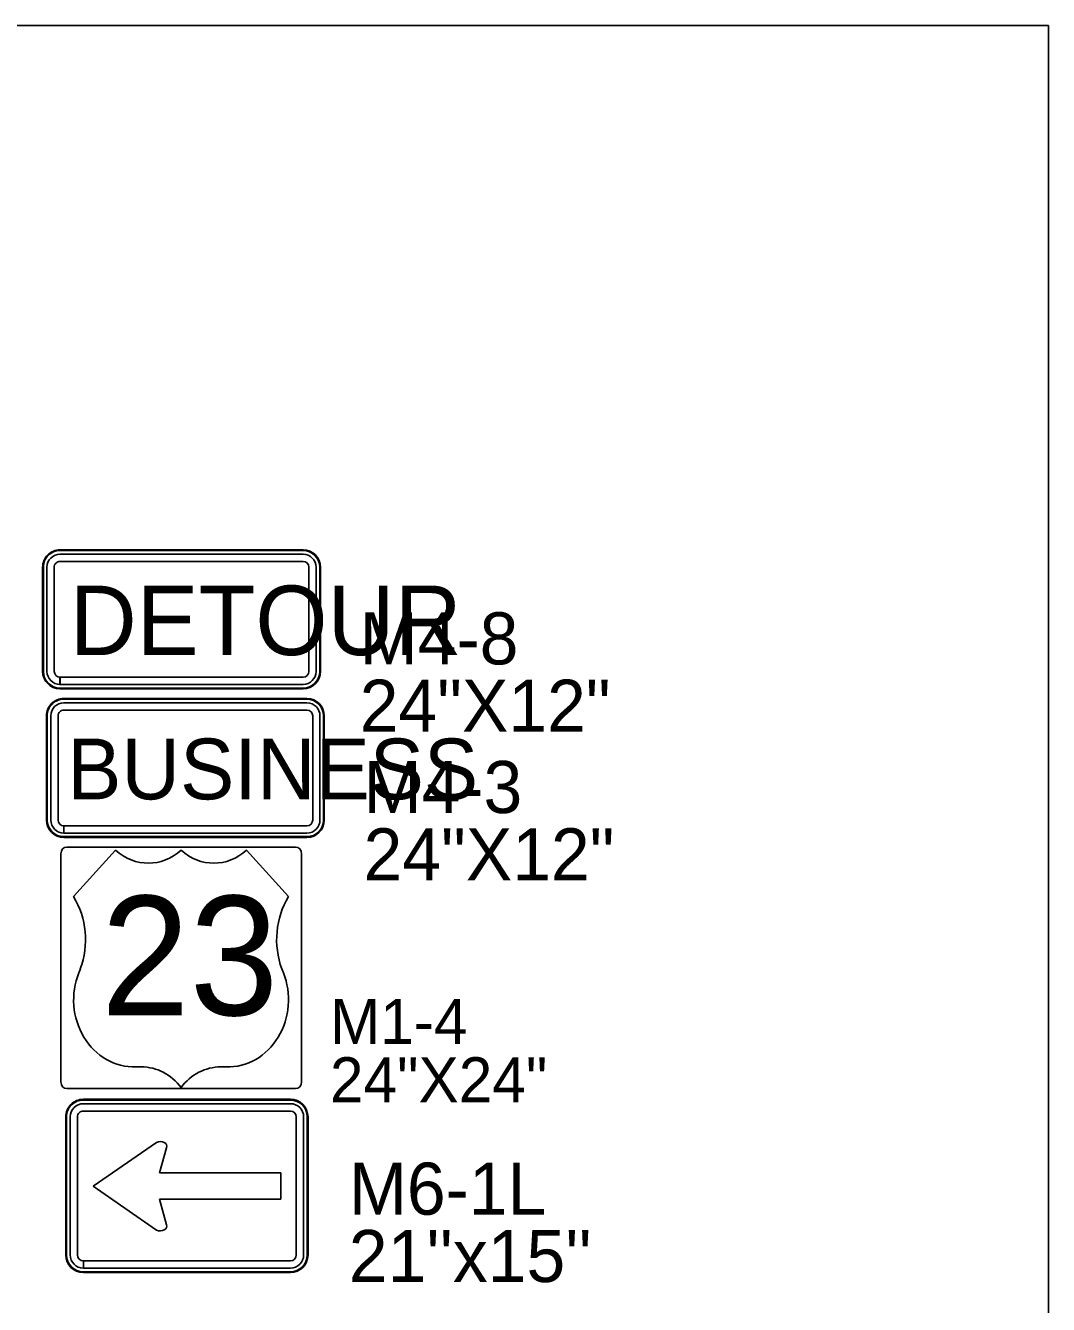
# Model space of a CAD drawing. Extents: x 886234 to 968767, y 455416 to 684046.
# Drawn here: x 964172 to 968767, y 540138 to 545883 of the extents above; entities that cross this region are included whole.
import ezdxf

# ---------------------------------------------------------------- set-up
doc = ezdxf.new("R2010")
doc.units = 0
for name, color, linetype in [('Scratch_Level_3', 7, 'Continuous'), ('TC DEV SIGN BLACK 239', 7, 'Continuous'), ('TC DEV SIGN BLACK ZERO', 7, 'Continuous'), ('TC DEV SIGN ORANGE', 7, 'Continuous'), ('TC DEV SIGN WHITE', 7, 'Continuous')]:
    doc.layers.add(name, color=color, linetype=linetype)

msp = doc.modelspace()

# ---------------------------------------------------------------- linework, layer by layer
at = {"layer": 'Scratch_Level_3'}
msp.add_lwpolyline([(933999.3, 545882.8), (968767.2, 545882.8), (968767.2, 536165.1), (933999.3, 536165.1)], close=True, dxfattribs=at)
at = {"layer": 'TC DEV SIGN BLACK 239'}
for p, q in [((965435.8, 542840.3), (964343.6, 542840.3)), ((965435.8, 542807.8), (964343.6, 542807.8)), ((964285.1, 542781.8), (964285.1, 542313.8)), ((964317.6, 542781.8), (964317.6, 542313.8)), ((965461.8, 542313.8), (965461.8, 542781.8)), ((965494.3, 542313.8), (965494.3, 542781.8)), ((964343.6, 542255.3), (964343.6, 542287.8)), ((964343.9, 542287.8), (965435.8, 542287.8)), ((964343.9, 542287.8), (964343.9, 542255.3)), ((964343.9, 542255.3), (965435.8, 542255.3)), ((965384.5, 542192.4), (964357.5, 542192.4)), ((964576.4, 542178.1), (964576.4, 542178.1)), ((964870.3, 542178.1), (964870.3, 542178.1)), ((964330.2, 542162.3), (964330.2, 541137.1)), ((965411.8, 541137.1), (965411.8, 542162.3)), ((965353.1, 541969.5), (965353.1, 541969.5)), ((964418.3, 541645), (964417.6, 541645)), ((965323, 541645), (965322.2, 541645)), ((964692.1, 541204.6), (964650.2, 541204.8)), ((965090.4, 541204.8), (965048.4, 541204.6)), ((964357.5, 541107), (965384.5, 541107)), ((964870.3, 541111.9), (964870.3, 541111.9)), ((965361.5, 541039.4), (964431.3, 541039.4)), ((964372, 540980.1), (964371.9, 540359.9)), ((964404.9, 540980.1), (964404.9, 540359.9)), ((965361.5, 541006.4), (964431.3, 541006.4)), ((965387.9, 540359.9), (965387.9, 540980.1)), ((965420.8, 540359.9), (965420.8, 540980.1)), ((964760.6, 540865.6), (964474.6, 540668.7)), ((964773, 540729.4), (964805.3, 540841.7)), ((965318.8, 540729.4), (964773, 540729.4)), ((965318.8, 540610), (965318.8, 540729.4)), ((964474.6, 540668.7), (964760.6, 540471.7)), ((964805.3, 540495.7), (964773.1, 540610)), ((964773.1, 540610), (965318.8, 540610)), ((964431.3, 540300.5), (964431.3, 540333.5)), ((964431.6, 540333.5), (965361.5, 540333.5)), ((964431.6, 540333.5), (964431.6, 540300.5)), ((964431.6, 540300.5), (965361.5, 540300.5))]:
    msp.add_line(p, q, dxfattribs=at)
for points in [[(964357.5, 542192.4), (965384.5, 542192.4)], [(964387.5, 541969.5), (964387.5, 541969.5), (964576.4, 542178.1)], [(965164.1, 542178.1), (965164.1, 542178.1), (965353.1, 541969.5)], [(964330.2, 541137.1), (964330.2, 542162.3)], [(965411.8, 542162.3), (965411.8, 541137.1)], [(965384.5, 541107), (964357.5, 541107)]]:
    msp.add_lwpolyline(points, dxfattribs=at)
for centre, major_axis, ratio, start_param, end_param in [((964343.6, 542781.8), (58.5, 0), 0.999865, 1.570796, 3.141593), ((964343.6, 542781.8), (26, 0), 0.999865, 1.570796, 3.141593), ((965435.8, 542781.8), (58.5, 0), 0.999865, 0, 1.570796), ((965435.8, 542781.8), (26, 0), 0.999865, 0, 1.570796), ((964343.6, 542313.8), (58.5, 0), 0.999865, 3.141593, 4.712389), ((964343.6, 542313.8), (26, 0), 0.999865, 3.141593, 4.712389), ((965435.8, 542313.8), (58.5, 0), 0.999865, 4.712389, 6.283185), ((965435.8, 542313.8), (26, 0), 0.999865, 4.712389, 6.283185), ((964357.5, 542162.3), (0, -30.1), 0.905624, 3.141593, 4.712389), ((964357.5, 542162.3), (0, -30.1), 0.905624, 3.141593, 4.712389), ((964723.3, 542374.8), (0, -255), 0.905624, 5.593452, 6.972919), ((965017.2, 542374.8), (0, -255), 0.905624, 5.593452, 6.972919), ((965384.5, 542162.3), (0, 30.1), 0.905624, 4.712389, 6.283185), ((965384.5, 542162.3), (0, 30.1), 0.905624, 4.712389, 6.283185), ((964125.9, 541775.9), (0, -347.7), 0.905624, 1.184601, 2.161129), ((965614.6, 541775.9), (0, -347.7), 0.905624, 4.122057, 5.098584), ((964660.4, 541505.9), (0, 301.3), 0.905624, 1.091068, 3.104197), ((965080.2, 541505.9), (0, 301.3), 0.905624, 3.178989, 5.192118), ((964692.1, 540949.7), (0, 255), 0.905624, 5.402164, 6.283185), ((965048.4, 540949.7), (0, -255), 0.905624, 3.141593, 4.022614), ((964357.5, 541137.1), (0, -30.1), 0.905624, 4.712389, 6.283185), ((964357.5, 541137.1), (0, -30.1), 0.905624, 4.712389, 6.283185), ((965384.5, 541137.1), (0, 30.1), 0.905624, 3.141593, 4.712389), ((965384.5, 541137.1), (0, 30.1), 0.905624, 3.141593, 4.712389), ((964431.3, 540980.1), (59.3, 0), 0.999865, 1.570796, 3.141593), ((965361.5, 540980.1), (59.3, 0), 0.999865, 0, 1.570796), ((964431.3, 540980.1), (26.4, 0), 0.999865, 1.570796, 3.141593), ((965361.5, 540980.1), (26.4, 0), 0.999865, 0, 1.570796), ((964777.2, 540848.1), (-29.4, 0), 0.720018, 2.830616, 5.313575), ((964777.2, 540489.2), (-29.4, 0), 0.720018, 0.969609, 3.452568), ((964431.3, 540359.9), (59.3, 0), 0.999865, 3.141593, 4.712389), ((964431.3, 540359.9), (26.4, 0), 0.999865, 3.141593, 4.712389), ((965361.5, 540359.9), (59.3, 0), 0.999865, 4.712389, 6.283185), ((965361.5, 540359.9), (26.4, 0), 0.999865, 4.712389, 6.283185)]:
    msp.add_ellipse(centre, major_axis=major_axis, ratio=ratio, start_param=start_param, end_param=end_param, dxfattribs=at)
at = {"layer": 'TC DEV SIGN BLACK ZERO'}
for p, q in [((965418.5, 543527.5), (964326.3, 543527.5)), ((964326.3, 543524.3), (964326.3, 543524.3)), ((965418.5, 543524.2), (964326.3, 543524.3)), ((965418.5, 543508), (964326.3, 543508)), ((965418.5, 543524.2), (965418.5, 543524.3)), ((964248.3, 543449.5), (964248.3, 542981.5)), ((964251.5, 543449.5), (964251.5, 542981.5)), ((964251.5, 543449.5), (964251.6, 543449.5)), ((964267.8, 543449.5), (964267.8, 542981.5)), ((964300.3, 543449.5), (964300.3, 542981.5)), ((965418.5, 543475.5), (964326.3, 543475.5)), ((965444.5, 542981.5), (965444.5, 543449.5)), ((965477, 542981.5), (965477, 543449.5)), ((965493.2, 543449.5), (965493.3, 543449.5)), ((965493.3, 542981.5), (965493.3, 543449.5)), ((965496.5, 542981.5), (965496.5, 543449.5)), ((964251.6, 542981.5), (964251.5, 542981.5)), ((965493.3, 542981.5), (965493.2, 542981.5)), ((964326.3, 542923), (964326.3, 542955.5)), ((964326.6, 542955.5), (965418.5, 542955.5)), ((964326.6, 542955.5), (964326.6, 542923)), ((964326.6, 542923), (965418.5, 542923)), ((964326.3, 542903.5), (964326.3, 542906.8)), ((964326.3, 542906.8), (964326.3, 542906.8)), ((964326.4, 542906.8), (965418.5, 542906.8)), ((964326.4, 542906.8), (964326.4, 542903.5)), ((964326.4, 542903.5), (965418.5, 542903.5)), ((965418.5, 542906.8), (965418.5, 542906.8)), ((965435.8, 542859.8), (964343.6, 542859.8)), ((964343.6, 542856.6), (964343.6, 542856.6)), ((965435.8, 542856.5), (964343.6, 542856.6)), ((965435.8, 542856.5), (965435.8, 542856.6)), ((964265.6, 542781.8), (964265.6, 542313.8)), ((964268.8, 542781.8), (964268.8, 542313.8)), ((964268.8, 542781.8), (964268.8, 542781.8)), ((965510.5, 542781.8), (965510.5, 542781.8)), ((965510.5, 542313.8), (965510.5, 542781.8)), ((965513.8, 542313.8), (965513.8, 542781.8)), ((964268.8, 542313.8), (964268.8, 542313.8)), ((965510.5, 542313.8), (965510.5, 542313.8)), ((964343.6, 542235.8), (964343.6, 542239.1)), ((964343.6, 542239.1), (964343.6, 542239.1)), ((964343.7, 542239.1), (965435.8, 542239.1)), ((964343.7, 542239.1), (964343.7, 542235.8)), ((964343.7, 542235.8), (965435.8, 542235.8)), ((965435.8, 542239.1), (965435.8, 542239.1)), ((965361.5, 541059.2), (964431.3, 541059.2)), ((964431.3, 541055.9), (964431.3, 541055.9)), ((965361.5, 541055.9), (964431.3, 541055.9)), ((965361.5, 541055.9), (965361.5, 541055.9)), ((964352.2, 540980.1), (964352.2, 540359.9)), ((964355.4, 540980.1), (964355.4, 540359.9)), ((964355.4, 540980.1), (964355.5, 540980.1)), ((965437.3, 540980.1), (965437.4, 540980.1)), ((965437.3, 540359.9), (965437.4, 540980.1)), ((965440.6, 540359.9), (965440.6, 540980.1)), ((964355.4, 540359.9), (964355.4, 540359.9)), ((965437.3, 540359.9), (965437.3, 540359.9)), ((964431.3, 540280.8), (964431.3, 540284.1)), ((964431.3, 540284.1), (964431.3, 540284.1)), ((964431.3, 540284.1), (965361.5, 540284.1)), ((964431.3, 540284.1), (964431.3, 540280.8)), ((964431.3, 540280.8), (965361.5, 540280.8)), ((965361.5, 540284.1), (965361.5, 540284.1))]:
    msp.add_line(p, q, dxfattribs=at)
for centre, major_axis, start_param, end_param in [((964326.3, 543449.5), (78, 0), 1.570796, 3.141593), ((964326.3, 543449.5), (74.8, 0), 1.570796, 3.141593), ((964326.3, 543449.5), (58.5, 0), 1.570796, 3.141593), ((965418.5, 543449.5), (78, 0), 0, 1.570796), ((965418.5, 543449.5), (74.8, 0), 0, 1.570796), ((965418.5, 543449.5), (58.5, 0), 0, 1.570796), ((964326.3, 543449.5), (26, 0), 1.570796, 3.141593), ((965418.5, 543449.5), (26, 0), 0, 1.570796), ((964326.3, 542981.5), (78, 0), 3.141593, 4.712389), ((964326.3, 542981.5), (74.8, 0), 3.141593, 4.712389), ((964326.3, 542981.5), (58.5, 0), 3.141593, 4.712389), ((964326.3, 542981.5), (26, 0), 3.141593, 4.712389), ((965418.5, 542981.5), (58.5, 0), 4.712389, 6.283185), ((965418.5, 542981.5), (26, 0), 4.712389, 6.283185), ((965418.5, 542981.5), (78, 0), 4.712389, 6.283185), ((965418.5, 542981.5), (74.8, 0), 4.712389, 6.283185), ((964343.6, 542781.8), (78, 0), 1.570796, 3.141593), ((964343.6, 542781.8), (74.8, 0), 1.570796, 3.141593), ((965435.8, 542781.8), (78, 0), 0, 1.570796), ((965435.8, 542781.8), (74.8, 0), 0, 1.570796), ((964343.6, 542313.8), (78, 0), 3.141593, 4.712389), ((964343.6, 542313.8), (74.8, 0), 3.141593, 4.712389), ((965435.8, 542313.8), (78, 0), 4.712389, 6.283185), ((965435.8, 542313.8), (74.8, 0), 4.712389, 6.283185), ((964431.3, 540980.1), (79.1, 0), 1.570796, 3.141593), ((964431.3, 540980.1), (75.8, 0), 1.570796, 3.141593), ((965361.5, 540980.1), (79.1, 0), 0, 1.570796), ((965361.5, 540980.1), (75.8, 0), 0, 1.570796), ((964431.3, 540359.9), (79.1, 0), 3.141593, 4.712389), ((964431.3, 540359.9), (75.8, 0), 3.141593, 4.712389), ((965361.5, 540359.9), (79.1, 0), 4.712389, 6.283185), ((965361.5, 540359.9), (75.8, 0), 4.712389, 6.283185)]:
    msp.add_ellipse(centre, major_axis=major_axis, ratio=0.999865, start_param=start_param, end_param=end_param, dxfattribs=at)
at = {"layer": 'TC DEV SIGN ORANGE'}
for p, q in [((965418.5, 543527.5), (964326.3, 543527.5)), ((964248.3, 543449.5), (964248.3, 542981.5)), ((965496.5, 542981.5), (965496.5, 543449.5)), ((964326.3, 542903.5), (965418.5, 542903.5))]:
    msp.add_line(p, q, dxfattribs=at)
for centre, start_param, end_param in [((964326.3, 543449.5), 1.570796, 3.141593), ((965418.5, 543449.5), 0, 1.570796), ((964326.3, 542981.5), 3.141593, 4.712389), ((965418.5, 542981.5), 4.712389, 6.283185)]:
    msp.add_ellipse(centre, major_axis=(78, 0), ratio=0.999865, start_param=start_param, end_param=end_param, dxfattribs=at)
at = {"layer": 'TC DEV SIGN WHITE'}
for p, q in [((965435.8, 542859.8), (964343.6, 542859.8)), ((964265.6, 542781.8), (964265.6, 542313.8)), ((965513.8, 542313.8), (965513.8, 542781.8)), ((964343.6, 542235.8), (965435.8, 542235.8)), ((964387.5, 541969.5), (964576.4, 542178.1)), ((964576.4, 542178.1), (964387.5, 541969.5)), ((965164.1, 542178.1), (965353.1, 541969.5)), ((965353.1, 541969.5), (965164.1, 542178.1)), ((964417.6, 541645), (964418.3, 541645)), ((964650.2, 541204.8), (964692.1, 541204.6)), ((965048.4, 541204.6), (965090.4, 541204.8)), ((964870.3, 541111.9), (964870.3, 541111.9)), ((965361.5, 541059.2), (964431.3, 541059.2)), ((964352.2, 540980.1), (964352.2, 540359.9)), ((965440.6, 540359.9), (965440.6, 540980.1)), ((964431.3, 540280.8), (965361.5, 540280.8))]:
    msp.add_line(p, q, dxfattribs=at)
for points in [[(964870.3, 542178.1), (964870.3, 542178.1)], [(965322.2, 541645), (965323, 541645)]]:
    msp.add_lwpolyline(points, dxfattribs=at)
for centre, major_axis, ratio, start_param, end_param in [((964343.6, 542781.8), (78, 0), 0.999865, 1.570796, 3.141593), ((965435.8, 542781.8), (78, 0), 0.999865, 0, 1.570796), ((964343.6, 542313.8), (78, 0), 0.999865, 3.141593, 4.712389), ((965435.8, 542313.8), (78, 0), 0.999865, 4.712389, 6.283185), ((964723.3, 542374.8), (0, -255), 0.905624, 5.593452, 6.972919), ((964723.3, 542374.8), (0, -255), 0.905624, 5.593452, 6.972919), ((965017.2, 542374.8), (0, -255), 0.905624, 5.593452, 6.972919), ((965017.2, 542374.8), (0, -255), 0.905624, 5.593452, 6.972919), ((964125.9, 541775.9), (0, -347.7), 0.905624, 1.184601, 2.161129), ((964125.9, 541775.9), (0, -347.7), 0.905624, 1.184601, 2.161129), ((965614.6, 541775.9), (0, -347.7), 0.905624, 4.122057, 5.098584), ((965614.6, 541775.9), (0, -347.7), 0.905624, 4.122057, 5.098584), ((964660.4, 541505.9), (0, 301.3), 0.905624, 1.091068, 3.104197), ((964660.4, 541505.9), (0, 301.3), 0.905624, 1.091068, 3.104197), ((965080.2, 541505.9), (0, 301.3), 0.905624, 3.178989, 5.192118), ((965080.2, 541505.9), (0, 301.3), 0.905624, 3.178989, 5.192118), ((964692.1, 540949.7), (0, 255), 0.905624, 5.402164, 6.283185), ((964692.1, 540949.7), (0, 255), 0.905624, 5.402164, 6.283185), ((965048.4, 540949.7), (0, -255), 0.905624, 3.141593, 4.022614), ((965048.4, 540949.7), (0, -255), 0.905624, 3.141593, 4.022614), ((964431.3, 540980.1), (79.1, 0), 0.999865, 1.570796, 3.141593), ((965361.5, 540980.1), (79.1, 0), 0.999865, 0, 1.570796), ((964431.3, 540359.9), (79.1, 0), 0.999865, 3.141593, 4.712389), ((965361.5, 540359.9), (79.1, 0), 0.999865, 4.712389, 6.283185)]:
    msp.add_ellipse(centre, major_axis=major_axis, ratio=ratio, start_param=start_param, end_param=end_param, dxfattribs=at)

# ---------------------------------------------------------------- texts
at = {"layer": 'TC DEV SIGN BLACK 239'}
for s, height, p in [('BUSINESS', 273, (964358.7, 542406.6)), ('23', 536.04, (964510, 541436.9))]:
    msp.add_text(s, height=height, rotation=360, dxfattribs=at).set_placement(p)
at = {"layer": 'TC DEV SIGN BLACK ZERO'}
for s, height, p in [('DETOUR', 312, (964369.6, 543054.8)), ('M4-8', 234, (965673, 543012.8)), ('24"X12"', 234, (965673, 542710.2)), ('M4-3', 234, (965690.3, 542345.1)), ('24"X12"', 234, (965690.3, 542042.5)), ('M1-4', 202.8, (965539.1, 541307.5)), ('24"X24"', 202.8, (965539.1, 541045.2)), ('M6-1L', 234, (965624.2, 540540.7)), ("21''x15''", 234, (965624.2, 540238.1))]:
    msp.add_text(s, height=height, rotation=360, dxfattribs=at).set_placement(p)

doc.saveas('drawing.dxf')
